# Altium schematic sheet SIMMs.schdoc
size 438 x 169 mm
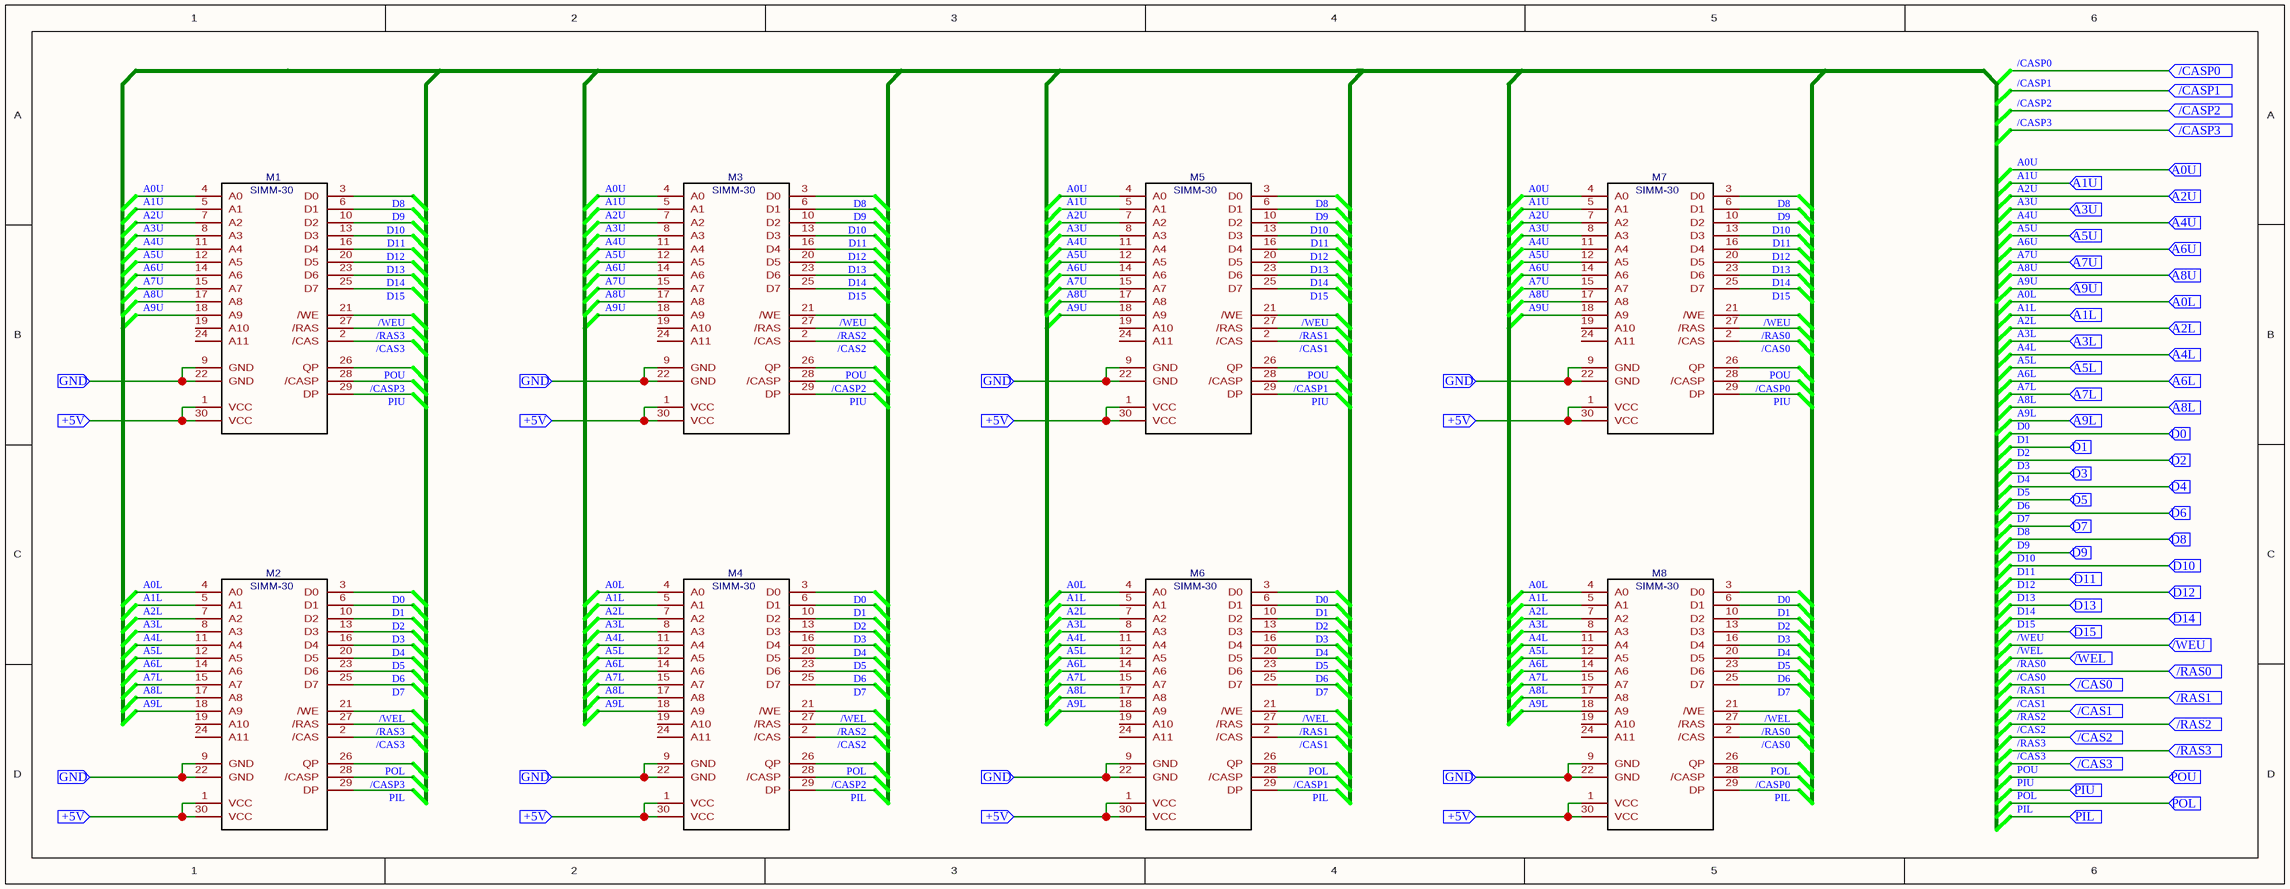
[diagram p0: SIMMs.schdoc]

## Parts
M1  SIMM-30  [SIMM30_NO_SILK]
M2  SIMM-30  [SIMM30_NO_SILK]
M3  SIMM-30  [SIMM30_NO_SILK]
M4  SIMM-30  [SIMM30_NO_SILK]
M5  SIMM-30  [SIMM30_NO_SILK]
M6  SIMM-30  [SIMM30_NO_SILK]
M7  SIMM-30  [SIMM30_NO_SILK]
M8  SIMM-30  [SIMM30_NO_SILK]

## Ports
+5V (in), /CAS0 (in), /CAS1 (in), /CAS2 (in), /CAS3 (in), /CASP0 (in), /CASP1 (in), /CASP2 (in), /CASP3 (in), /RAS0 (in), /RAS1 (in), /RAS2 (in), /RAS3 (in), /WEL (in), /WEU (in), A0L (in), A0U (in), A1L (in), A1U (in), A2L (in), A2U (in), A3L (in), A3U (in), A4L (in), A4U (in), A5L (in), A5U (in), A6L (in), A6U (in), A7L (in), A7U (in), A8L (in), A8U (in), A9L (in), A9U (in), D0 (in), D1 (in), D2 (in), D3 (in), D4 (in), D5 (in), D6 (in), D7 (in), D8 (in), D9 (in), D10 (in), D11 (in), D12 (in), D13 (in), D14 (in), D15 (in), GND (in), PIL (in), PIU (in), POL (in), POU (in)

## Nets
+5V: M1.1(VCC) M1.30(VCC) M2.1(VCC) M2.30(VCC) M3.1(VCC) M3.30(VCC) M4.1(VCC) M4.30(VCC) M5.1(VCC) M5.30(VCC) M6.1(VCC) M6.30(VCC) M7.1(VCC) M7.30(VCC) M8.1(VCC) M8.30(VCC) ; port +5V
/CAS0: M7.2(/CAS) M8.2(/CAS) ; port /CAS0
/CAS1: M5.2(/CAS) M6.2(/CAS) ; port /CAS1
/CAS2: M3.2(/CAS) M4.2(/CAS) ; port /CAS2
/CAS3: M1.2(/CAS) M2.2(/CAS) ; port /CAS3
/CASP0: M7.28(/CASP) M8.28(/CASP) ; port /CASP0
/CASP1: M5.28(/CASP) M6.28(/CASP) ; port /CASP1
/CASP2: M3.28(/CASP) M4.28(/CASP) ; port /CASP2
/CASP3: M1.28(/CASP) M2.28(/CASP) ; port /CASP3
/RAS0: M7.27(/RAS) M8.27(/RAS) ; port /RAS0
/RAS1: M5.27(/RAS) M6.27(/RAS) ; port /RAS1
/RAS2: M3.27(/RAS) M4.27(/RAS) ; port /RAS2
/RAS3: M1.27(/RAS) M2.27(/RAS) ; port /RAS3
/WEL: M2.21(/WE) M4.21(/WE) M6.21(/WE) M8.21(/WE) ; port /WEL
/WEU: M1.21(/WE) M3.21(/WE) M5.21(/WE) M7.21(/WE) ; port /WEU
A0L: M2.4(A0) M4.4(A0) M6.4(A0) M8.4(A0) ; port A0L
A0U: M1.4(A0) M3.4(A0) M5.4(A0) M7.4(A0) ; port A0U
A1L: M2.5(A1) M4.5(A1) M6.5(A1) M8.5(A1) ; port A1L
A1U: M1.5(A1) M3.5(A1) M5.5(A1) M7.5(A1) ; port A1U
A2L: M2.7(A2) M4.7(A2) M6.7(A2) M8.7(A2) ; port A2L
A2U: M1.7(A2) M3.7(A2) M5.7(A2) M7.7(A2) ; port A2U
A3L: M2.8(A3) M4.8(A3) M6.8(A3) M8.8(A3) ; port A3L
A3U: M1.8(A3) M3.8(A3) M5.8(A3) M7.8(A3) ; port A3U
A4L: M2.11(A4) M4.11(A4) M6.11(A4) M8.11(A4) ; port A4L
A4U: M1.11(A4) M3.11(A4) M5.11(A4) M7.11(A4) ; port A4U
A5L: M2.12(A5) M4.12(A5) M6.12(A5) M8.12(A5) ; port A5L
A5U: M1.12(A5) M3.12(A5) M5.12(A5) M7.12(A5) ; port A5U
A6L: M2.14(A6) M4.14(A6) M6.14(A6) M8.14(A6) ; port A6L
A6U: M1.14(A6) M3.14(A6) M5.14(A6) M7.14(A6) ; port A6U
A7L: M2.15(A7) M4.15(A7) M6.15(A7) M8.15(A7) ; port A7L
A7U: M1.15(A7) M3.15(A7) M5.15(A7) M7.15(A7) ; port A7U
A8L: M2.17(A8) M4.17(A8) M6.17(A8) M8.17(A8) ; port A8L
A8U: M1.17(A8) M3.17(A8) M5.17(A8) M7.17(A8) ; port A8U
A9L: M2.18(A9) M4.18(A9) M6.18(A9) M8.18(A9) ; port A9L
A9U: M1.18(A9) M3.18(A9) M5.18(A9) M7.18(A9) ; port A9U
D0: M2.3(D0) M4.3(D0) M6.3(D0) M8.3(D0) ; port D0
D1: M2.6(D1) M4.6(D1) M6.6(D1) M8.6(D1) ; port D1
D2: M2.10(D2) M4.10(D2) M6.10(D2) M8.10(D2) ; port D2
D3: M2.13(D3) M4.13(D3) M6.13(D3) M8.13(D3) ; port D3
D4: M2.16(D4) M4.16(D4) M6.16(D4) M8.16(D4) ; port D4
D5: M2.20(D5) M4.20(D5) M6.20(D5) M8.20(D5) ; port D5
D6: M2.23(D6) M4.23(D6) M6.23(D6) M8.23(D6) ; port D6
D7: M2.25(D7) M4.25(D7) M6.25(D7) M8.25(D7) ; port D7
D8: M1.3(D0) M3.3(D0) M5.3(D0) M7.3(D0) ; port D8
D9: M1.6(D1) M3.6(D1) M5.6(D1) M7.6(D1) ; port D9
D10: M1.10(D2) M3.10(D2) M5.10(D2) M7.10(D2) ; port D10
D11: M1.13(D3) M3.13(D3) M5.13(D3) M7.13(D3) ; port D11
D12: M1.16(D4) M3.16(D4) M5.16(D4) M7.16(D4) ; port D12
D13: M1.20(D5) M3.20(D5) M5.20(D5) M7.20(D5) ; port D13
D14: M1.23(D6) M3.23(D6) M5.23(D6) M7.23(D6) ; port D14
D15: M1.25(D7) M3.25(D7) M5.25(D7) M7.25(D7) ; port D15
GND: M1.9(GND) M1.22(GND) M2.9(GND) M2.22(GND) M3.9(GND) M3.22(GND) M4.9(GND) M4.22(GND) M5.9(GND) M5.22(GND) M6.9(GND) M6.22(GND) M7.9(GND) M7.22(GND) M8.9(GND) M8.22(GND) ; port GND
PIL: M2.29(DP) M4.29(DP) M6.29(DP) M8.29(DP) ; port PIL
PIU: M1.29(DP) M3.29(DP) M5.29(DP) M7.29(DP) ; port PIU
POL: M2.26(QP) M4.26(QP) M6.26(QP) M8.26(QP) ; port POL
POU: M1.26(QP) M3.26(QP) M5.26(QP) M7.26(QP) ; port POU

Not connected (* = marked no-connect by the designer): M1 19(A10) 24(A11); M2 19(A10) 24(A11); M3 19(A10) 24(A11); M4 19(A10) 24(A11); M5 19(A10) 24(A11); M6 19(A10) 24(A11); M7 19(A10) 24(A11); M8 19(A10) 24(A11)

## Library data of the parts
M1-M8 = SIMM-30: Contributor: William Tooker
